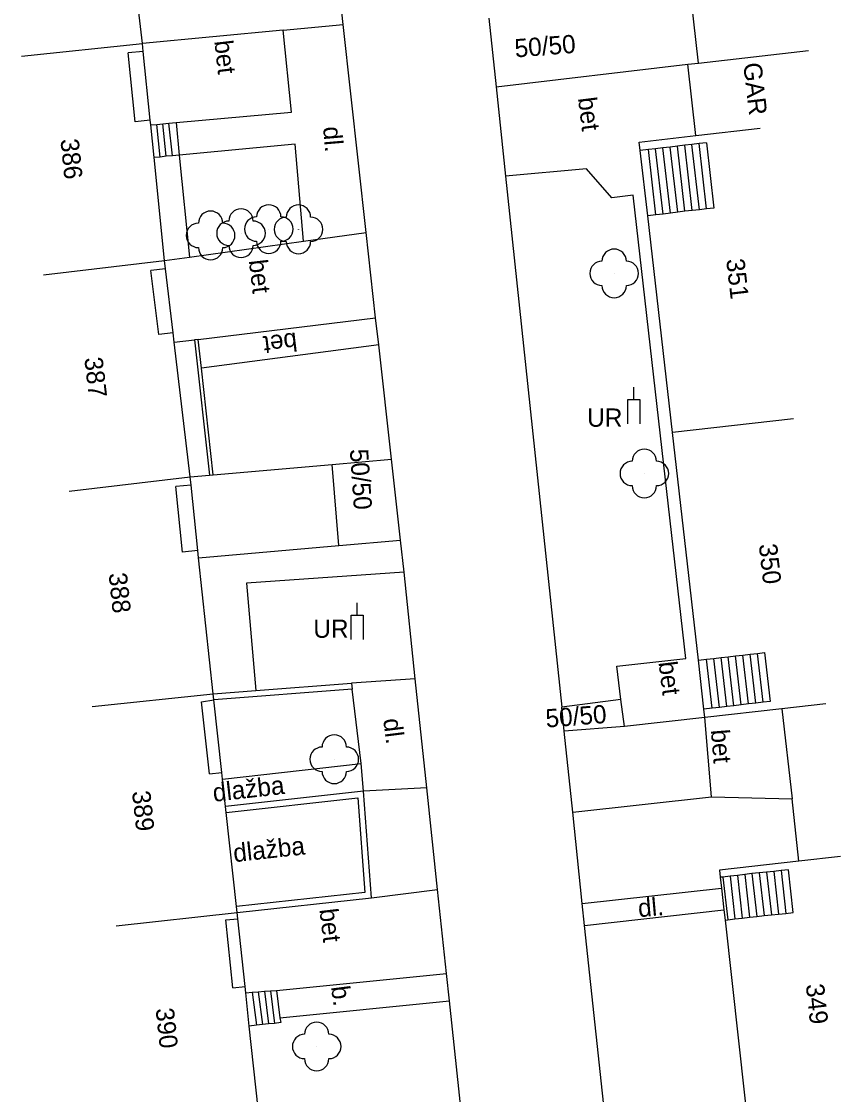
# Model space of a CAD drawing. Extents: x -544674 to -541478, y -1199076 to -1195527.
# Drawn here: x -542502.7 to -542469.05, y -1198467.22 to -1198423.14 of the extents above; entities that cross this region are included whole.
import ezdxf

# ---------------------------------------------------------------- set-up
doc = ezdxf.new("R2010")
doc.units = 0
for name, color, linetype in [('BUDOVY_MĚŘ', 7, 'Continuous'), ('POMOC_POPIS', 7, 'Continuous'), ('ROZHRANÍ_PLOCH', 7, 'Continuous'), ('ZELEŇ', 7, 'Continuous'), ('ZN_DOPLŇKOVÉ', 7, 'Continuous'), ('Č_POPIS_ORIENT', 7, 'Continuous')]:
    doc.layers.add(name, color=color, linetype=linetype)

msp = doc.modelspace()

# ---------------------------------------------------------------- linework, layer by layer
at = {"layer": 'BUDOVY_MĚŘ'}
for points in [[(-542497.73, -1198424.05), (-542498.24, -1198419.72)], [(-542502.7, -1198424.56), (-542497.73, -1198424.05)], [(-542497.7, -1198424.37), (-542497.73, -1198424.05)], [(-542497.41, -1198427.2), (-542497.7, -1198424.37)], [(-542474.89, -1198424.85), (-542470.36, -1198424.33)], [(-542475.33, -1198424.9), (-542474.89, -1198424.85)], [(-542474.99, -1198427.83), (-542475.33, -1198424.9)], [(-542497.39, -1198427.39), (-542497.41, -1198427.2)], [(-542497.25, -1198428.73), (-542497.39, -1198427.39)], [(-542474.99, -1198427.83), (-542472.35, -1198427.53)], [(-542477.28, -1198428.44), (-542477.32, -1198428.1), (-542474.99, -1198427.83)], [(-542476.97, -1198431.12), (-542477.28, -1198428.44)], [(-542496.82, -1198432.96), (-542497.25, -1198428.73)], [(-542475.95, -1198440.02), (-542476.97, -1198431.12)], [(-542501.79, -1198433.55), (-542496.82, -1198432.96)], [(-542496.78, -1198433.3), (-542496.82, -1198432.96)], [(-542496.47, -1198435.93), (-542496.78, -1198433.3)], [(-542496.42, -1198436.31), (-542496.47, -1198435.93)], [(-542495.77, -1198441.85), (-542496.42, -1198436.31)], [(-542470.98, -1198439.46), (-542475.95, -1198440.02)], [(-542474.89, -1198449.38), (-542475.95, -1198440.02)], [(-542500.74, -1198442.44), (-542495.77, -1198441.85)], [(-542495.73, -1198442.19), (-542495.77, -1198441.85)], [(-542495.45, -1198444.87), (-542495.73, -1198442.19)], [(-542495.42, -1198445.17), (-542495.45, -1198444.87)], [(-542494.83, -1198450.76), (-542495.42, -1198445.17)], [(-542474.66, -1198451.39), (-542474.89, -1198449.38)], [(-542499.8, -1198451.28), (-542494.83, -1198450.76)], [(-542494.8, -1198451.01), (-542494.83, -1198450.76)], [(-542494.47, -1198453.99), (-542494.8, -1198451.01)], [(-542474.62, -1198451.74), (-542474.66, -1198451.39)], [(-542471.46, -1198451.38), (-542474.62, -1198451.74)], [(-542469.65, -1198451.18), (-542471.46, -1198451.38)], [(-542494.44, -1198454.27), (-542494.47, -1198453.99)], [(-542494.32, -1198455.39), (-542494.44, -1198454.27)], [(-542494.29, -1198455.64), (-542494.32, -1198455.39)], [(-542493.87, -1198459.5), (-542494.29, -1198455.64)], [(-542470.76, -1198457.64), (-542474.02, -1198458), (-542473.99, -1198458.3)], [(-542469.05, -1198457.45), (-542470.76, -1198457.64)], [(-542472.09, -1198458.09), (-542472.39, -1198458.12)], [(-542471.79, -1198458.06), (-542472.09, -1198458.09)], [(-542471.49, -1198458.02), (-542471.79, -1198458.06)], [(-542471.3, -1198459.78), (-542471, -1198459.75), (-542471.19, -1198457.99), (-542471.49, -1198458.02)], [(-542473.88, -1198458.29), (-542473.99, -1198458.3)], [(-542473.99, -1198458.3), (-542473.94, -1198458.74)], [(-542473.58, -1198458.25), (-542473.88, -1198458.29)], [(-542473.28, -1198458.22), (-542473.58, -1198458.25)], [(-542472.98, -1198458.18), (-542473.28, -1198458.22)], [(-542472.69, -1198458.15), (-542472.98, -1198458.18)], [(-542472.39, -1198458.12), (-542472.69, -1198458.15)], [(-542473.94, -1198458.74), (-542473.84, -1198459.63)], [(-542498.81, -1198460.3), (-542493.84, -1198459.75)], [(-542493.84, -1198459.75), (-542493.87, -1198459.5)], [(-542493.81, -1198460), (-542493.84, -1198459.75)], [(-542473.84, -1198459.63), (-542473.79, -1198460.06)], [(-542472.49, -1198459.91), (-542472.19, -1198459.87)], [(-542472.19, -1198459.87), (-542471.89, -1198459.84)], [(-542471.89, -1198459.84), (-542471.6, -1198459.81)], [(-542471.6, -1198459.81), (-542471.3, -1198459.78)], [(-542493.51, -1198462.78), (-542493.81, -1198460)], [(-542473.79, -1198460.06), (-542473.68, -1198460.05)], [(-542473.79, -1198460.06), (-542472.71, -1198469.85)], [(-542473.68, -1198460.05), (-542473.39, -1198460.01)], [(-542473.39, -1198460.01), (-542473.09, -1198459.98)], [(-542473.09, -1198459.98), (-542472.79, -1198459.94)], [(-542472.79, -1198459.94), (-542472.49, -1198459.91)], [(-542493.48, -1198463.04), (-542493.51, -1198462.78)], [(-542493.34, -1198464.41), (-542493.48, -1198463.04)], [(-542494.76, -1198468.88), (-542492.88, -1198468.68), (-542493.34, -1198464.41)]]:
    msp.add_lwpolyline(points, dxfattribs=at)
at = {"layer": 'ROZHRANÍ_PLOCH'}
for points in [[(-542489.49, -1198423.27), (-542490.01, -1198418.46)], [(-542474.89, -1198424.85), (-542475.19, -1198422.17)], [(-542491.95, -1198423.5), (-542489.49, -1198423.27)], [(-542488.54, -1198431.81), (-542489.49, -1198423.27)], [(-542483.5, -1198423.01), (-542483.2, -1198425.83)], [(-542491.95, -1198423.5), (-542497.73, -1198424.05)], [(-542496.35, -1198427.29), (-542491.61, -1198426.86), (-542491.95, -1198423.5)], [(-542497.7, -1198424.37), (-542498.31, -1198424.43)], [(-542498.03, -1198427.27), (-542498.31, -1198424.43)], [(-542483.2, -1198425.83), (-542475.33, -1198424.9)], [(-542483.2, -1198425.83), (-542482.81, -1198429.49)], [(-542497.41, -1198427.2), (-542498.03, -1198427.27)], [(-542497.39, -1198427.39), (-542497.14, -1198427.37)], [(-542497.14, -1198427.37), (-542496.89, -1198427.34)], [(-542497, -1198428.71), (-542497.14, -1198427.37)], [(-542496.89, -1198427.34), (-542496.64, -1198427.32)], [(-542496.75, -1198428.68), (-542496.89, -1198427.34)], [(-542496.64, -1198427.32), (-542496.35, -1198427.29)], [(-542496.5, -1198428.66), (-542496.64, -1198427.32)], [(-542496.35, -1198427.29), (-542496.22, -1198428.63)], [(-542474.56, -1198428.13), (-542474.86, -1198428.16)], [(-542474.56, -1198428.13), (-542474.25, -1198430.81)], [(-542491.11, -1198432.17), (-542491.45, -1198428.18), (-542496.22, -1198428.63)], [(-542476.94, -1198428.4), (-542477.28, -1198428.44)], [(-542476.65, -1198428.37), (-542476.94, -1198428.4)], [(-542476.64, -1198431.08), (-542476.94, -1198428.4)], [(-542476.35, -1198428.33), (-542476.65, -1198428.37)], [(-542476.34, -1198431.05), (-542476.65, -1198428.37)], [(-542476.05, -1198428.3), (-542476.35, -1198428.33)], [(-542476.04, -1198431.01), (-542476.35, -1198428.33)], [(-542475.75, -1198428.26), (-542476.05, -1198428.3)], [(-542475.74, -1198430.98), (-542476.05, -1198428.3)], [(-542475.45, -1198428.22), (-542475.75, -1198428.26)], [(-542475.44, -1198430.94), (-542475.75, -1198428.26)], [(-542475.16, -1198428.19), (-542475.45, -1198428.22)], [(-542475.15, -1198430.91), (-542475.45, -1198428.22)], [(-542474.86, -1198428.16), (-542475.16, -1198428.19)], [(-542474.85, -1198430.88), (-542475.16, -1198428.19)], [(-542474.55, -1198430.84), (-542474.86, -1198428.16)], [(-542497, -1198428.71), (-542497.25, -1198428.73)], [(-542496.75, -1198428.68), (-542497, -1198428.71)], [(-542496.5, -1198428.66), (-542496.75, -1198428.68)], [(-542496.22, -1198428.63), (-542496.5, -1198428.66)], [(-542496.22, -1198428.63), (-542495.8, -1198432.82)], [(-542478.07, -1198451), (-542478.24, -1198449.63), (-542475.4, -1198449.31), (-542476.44, -1198440.16), (-542477.57, -1198430.28), (-542478.44, -1198430.38), (-542479.48, -1198429.2), (-542482.81, -1198429.49)], [(-542482.81, -1198429.49), (-542480.5, -1198451.31)], [(-542476.64, -1198431.08), (-542476.97, -1198431.12)], [(-542476.34, -1198431.05), (-542476.64, -1198431.08)], [(-542476.04, -1198431.01), (-542476.34, -1198431.05)], [(-542475.74, -1198430.98), (-542476.04, -1198431.01)], [(-542475.44, -1198430.94), (-542475.74, -1198430.98)], [(-542475.15, -1198430.91), (-542475.44, -1198430.94)], [(-542474.85, -1198430.88), (-542475.15, -1198430.91)], [(-542474.55, -1198430.84), (-542474.85, -1198430.88)], [(-542474.25, -1198430.81), (-542474.55, -1198430.84)], [(-542491.11, -1198432.17), (-542488.54, -1198431.81)], [(-542488.15, -1198435.31), (-542488.54, -1198431.81)], [(-542495.8, -1198432.82), (-542491.11, -1198432.17)], [(-542496.82, -1198432.96), (-542495.8, -1198432.82)], [(-542496.78, -1198433.3), (-542497.38, -1198433.37)], [(-542497.06, -1198436), (-542497.38, -1198433.37)], [(-542495.44, -1198436.2), (-542488.15, -1198435.31)], [(-542488.02, -1198436.43), (-542488.15, -1198435.31)], [(-542496.47, -1198435.93), (-542497.06, -1198436)], [(-542496.42, -1198436.31), (-542495.59, -1198436.22)], [(-542488.02, -1198436.43), (-542495.31, -1198437.39)], [(-542487.5, -1198441.12), (-542488.02, -1198436.43)], [(-542494.83, -1198441.77), (-542489.94, -1198441.34)], [(-542489.94, -1198441.34), (-542487.5, -1198441.12)], [(-542489.66, -1198444.67), (-542489.94, -1198441.34)], [(-542487.13, -1198444.45), (-542487.5, -1198441.12)], [(-542495.77, -1198441.85), (-542494.98, -1198441.78)], [(-542495.73, -1198442.19), (-542496.36, -1198442.25)], [(-542496.08, -1198444.94), (-542496.36, -1198442.25)], [(-542495.45, -1198444.87), (-542496.08, -1198444.94)], [(-542495.42, -1198445.17), (-542489.66, -1198444.67)], [(-542489.66, -1198444.67), (-542487.13, -1198444.45)], [(-542486.98, -1198445.76), (-542487.13, -1198444.45)], [(-542486.98, -1198445.76), (-542493.45, -1198446.22), (-542493.07, -1198450.62)], [(-542486.52, -1198450.15), (-542486.98, -1198445.76)], [(-542474.25, -1198449.31), (-542473.95, -1198449.27)], [(-542473.95, -1198449.27), (-542473.66, -1198449.24)], [(-542473.72, -1198451.28), (-542473.95, -1198449.27)], [(-542473.66, -1198449.24), (-542473.36, -1198449.2)], [(-542473.43, -1198451.25), (-542473.66, -1198449.24)], [(-542473.36, -1198449.2), (-542473.06, -1198449.17)], [(-542473.13, -1198451.22), (-542473.36, -1198449.2)], [(-542473.06, -1198449.17), (-542472.76, -1198449.13)], [(-542472.83, -1198451.18), (-542473.06, -1198449.17)], [(-542472.76, -1198449.13), (-542472.46, -1198449.1)], [(-542472.53, -1198451.15), (-542472.76, -1198449.13)], [(-542472.46, -1198449.1), (-542472.17, -1198449.07), (-542471.94, -1198451.08), (-542472.23, -1198451.11)], [(-542472.23, -1198451.11), (-542472.46, -1198449.1)], [(-542474.89, -1198449.38), (-542474.55, -1198449.34)], [(-542474.55, -1198449.34), (-542474.25, -1198449.31)], [(-542474.32, -1198451.35), (-542474.55, -1198449.34)], [(-542474.02, -1198451.32), (-542474.25, -1198449.31)], [(-542486.52, -1198450.15), (-542489.14, -1198450.32)], [(-542486.05, -1198454.63), (-542486.52, -1198450.15)], [(-542488.74, -1198453.63), (-542489.12, -1198450.57)], [(-542495.3, -1198451.09), (-542494.8, -1198451.01)], [(-542478.07, -1198451), (-542480.5, -1198451.31)], [(-542477.93, -1198452.1), (-542478.07, -1198451)], [(-542494.97, -1198454.05), (-542495.3, -1198451.09)], [(-542480.4, -1198452.29), (-542480.5, -1198451.31)], [(-542474.32, -1198451.35), (-542474.66, -1198451.39)], [(-542474.02, -1198451.32), (-542474.32, -1198451.35)], [(-542473.72, -1198451.28), (-542474.02, -1198451.32)], [(-542473.43, -1198451.25), (-542473.72, -1198451.28)], [(-542473.13, -1198451.22), (-542473.43, -1198451.25)], [(-542472.83, -1198451.18), (-542473.13, -1198451.22)], [(-542472.53, -1198451.15), (-542472.83, -1198451.18)], [(-542472.23, -1198451.11), (-542472.53, -1198451.15)], [(-542471.46, -1198451.38), (-542471.04, -1198455.08)], [(-542474.62, -1198451.74), (-542477.93, -1198452.1)], [(-542474.35, -1198454.99), (-542474.62, -1198451.74)], [(-542477.93, -1198452.1), (-542480.4, -1198452.29)], [(-542480.05, -1198455.63), (-542480.4, -1198452.29)], [(-542494.44, -1198454.27), (-542488.74, -1198453.63)], [(-542488.65, -1198454.76), (-542488.74, -1198453.63)], [(-542494.97, -1198454.05), (-542494.47, -1198453.99)], [(-542486.05, -1198454.63), (-542488.65, -1198454.76)], [(-542485.61, -1198458.8), (-542486.05, -1198454.63)], [(-542480.05, -1198455.63), (-542474.35, -1198454.99)], [(-542474.35, -1198454.99), (-542471.04, -1198455.08)], [(-542470.76, -1198457.64), (-542471.04, -1198455.08)], [(-542479.66, -1198459.38), (-542480.05, -1198455.63)], [(-542472.09, -1198458.09), (-542471.89, -1198459.84)], [(-542471.79, -1198458.06), (-542471.6, -1198459.81)], [(-542471.49, -1198458.02), (-542471.3, -1198459.78)], [(-542473.88, -1198458.29), (-542473.68, -1198460.05)], [(-542473.58, -1198458.25), (-542473.39, -1198460.01)], [(-542473.28, -1198458.22), (-542473.09, -1198459.98)], [(-542472.98, -1198458.18), (-542472.79, -1198459.94)], [(-542472.69, -1198458.15), (-542472.49, -1198459.91)], [(-542472.39, -1198458.12), (-542472.19, -1198459.87)], [(-542488.32, -1198459.14), (-542485.61, -1198458.8)], [(-542485.24, -1198462.25), (-542485.61, -1198458.8)], [(-542479.66, -1198459.38), (-542473.94, -1198458.74)], [(-542479.57, -1198460.28), (-542479.66, -1198459.38)], [(-542479.57, -1198460.28), (-542473.84, -1198459.63)], [(-542494.31, -1198460.05), (-542493.81, -1198460)], [(-542494.01, -1198462.84), (-542494.31, -1198460.05)], [(-542477.21, -1198482.02), (-542477.35, -1198480.95), (-542479.57, -1198460.28)], [(-542492.22, -1198462.95), (-542485.24, -1198462.25)], [(-542485.12, -1198463.37), (-542485.24, -1198462.25)], [(-542494.01, -1198462.84), (-542493.51, -1198462.78)], [(-542492.47, -1198462.97), (-542492.22, -1198462.95)], [(-542492.22, -1198462.95), (-542492.08, -1198464.07)], [(-542493.48, -1198463.04), (-542493.22, -1198463.02)], [(-542493.22, -1198463.02), (-542492.97, -1198463)], [(-542493.22, -1198463.02), (-542493.04, -1198464.38)], [(-542492.97, -1198463), (-542492.72, -1198462.98)], [(-542492.97, -1198463), (-542492.8, -1198464.35)], [(-542492.72, -1198462.98), (-542492.47, -1198462.97)], [(-542492.72, -1198462.98), (-542492.55, -1198464.32)], [(-542492.47, -1198462.97), (-542492.3, -1198464.3)], [(-542492.08, -1198464.07), (-542485.12, -1198463.37)], [(-542484.3, -1198471.13), (-542485.12, -1198463.37)], [(-542492.08, -1198464.07), (-542492.05, -1198464.27), (-542492.3, -1198464.3)], [(-542493.04, -1198464.38), (-542493.34, -1198464.41)], [(-542492.8, -1198464.35), (-542493.04, -1198464.38)], [(-542492.55, -1198464.32), (-542492.8, -1198464.35)], [(-542492.3, -1198464.3), (-542492.55, -1198464.32)]]:
    msp.add_lwpolyline(points, dxfattribs=at)
at = {"layer": 'ZELEŇ'}
for centre in [(-542494.93, -1198431.93), (-542493.68, -1198431.84), (-542492.54, -1198431.67), (-542491.32, -1198431.68), (-542478.35, -1198433.49), (-542477.11, -1198441.71), (-542489.85, -1198453.45), (-542490.57, -1198465.25)]:
    msp.add_circle(centre, 0.0005, dxfattribs=at)
for centre, start, end in [((-542492.54, -1198431.17), 0, 180), ((-542491.32, -1198431.18), 0, 180), ((-542494.93, -1198431.43), 0, 180), ((-542493.68, -1198431.34), 0, 180), ((-542493.04, -1198431.67), 90, 270), ((-542491.82, -1198431.68), 90, 270), ((-542492.04, -1198431.67), 270, 90), ((-542490.82, -1198431.68), 270, 90), ((-542495.43, -1198431.93), 90, 270), ((-542494.18, -1198431.84), 90, 270), ((-542494.43, -1198431.93), 270, 90), ((-542493.18, -1198431.84), 270, 90), ((-542494.93, -1198432.43), 180, 360), ((-542493.68, -1198432.34), 180, 360), ((-542492.54, -1198432.17), 180, 360), ((-542491.32, -1198432.18), 180, 360), ((-542478.35, -1198432.99), 0, 180), ((-542478.85, -1198433.49), 90, 270), ((-542477.85, -1198433.49), 270, 90), ((-542478.35, -1198433.99), 180, 360), ((-542477.11, -1198441.21), 0, 180), ((-542477.61, -1198441.71), 90, 270), ((-542476.61, -1198441.71), 270, 90), ((-542477.11, -1198442.21), 180, 360), ((-542489.85, -1198452.95), 0, 180), ((-542490.35, -1198453.45), 90, 270), ((-542489.35, -1198453.45), 270, 90), ((-542489.85, -1198453.95), 180, 360), ((-542490.57, -1198464.75), 0, 180), ((-542491.07, -1198465.25), 90, 270), ((-542490.07, -1198465.25), 270, 90), ((-542490.57, -1198465.75), 180, 360)]:
    msp.add_arc(centre, 0.5, start, end, dxfattribs=at)
at = {"layer": 'ZN_DOPLŇKOVÉ'}
for p, q in [((-542477.54, -1198438.67), (-542477.54, -1198438.17)), ((-542488.91, -1198447.53), (-542488.91, -1198447.03))]:
    msp.add_line(p, q, dxfattribs=at)
for points in [[(-542495.44, -1198436.2), (-542495.59, -1198436.22)], [(-542495.59, -1198436.22), (-542494.98, -1198441.78)], [(-542495.31, -1198437.39), (-542495.44, -1198436.2)], [(-542494.83, -1198441.77), (-542495.31, -1198437.39)], [(-542477.79, -1198439.67), (-542477.79, -1198438.67), (-542477.29, -1198438.67), (-542477.29, -1198439.67)], [(-542494.98, -1198441.78), (-542494.83, -1198441.77)], [(-542489.16, -1198448.53), (-542489.16, -1198447.53), (-542488.66, -1198447.53), (-542488.66, -1198448.53)], [(-542489.12, -1198450.57), (-542494.8, -1198451.01)], [(-542493.07, -1198450.62), (-542489.14, -1198450.32)], [(-542489.14, -1198450.32), (-542489.12, -1198450.57)], [(-542494.83, -1198450.76), (-542493.07, -1198450.62)], [(-542488.65, -1198454.76), (-542494.32, -1198455.39)], [(-542488.32, -1198459.14), (-542488.65, -1198454.76)], [(-542494.29, -1198455.64), (-542488.88, -1198455.04), (-542488.59, -1198458.92), (-542493.87, -1198459.5)], [(-542493.84, -1198459.75), (-542488.32, -1198459.14)]]:
    msp.add_lwpolyline(points, dxfattribs=at)

# ---------------------------------------------------------------- texts
at = {"layer": 'POMOC_POPIS'}
for s, rotation, p in [('50/50', 4.45, (-542482.41, -1198424.62)), ('bet', 276.57, (-542494.78, -1198423.95)), ('GAR', 276.56, (-542473.05, -1198424.87)), ('bet', 277.15, (-542479.84, -1198426.29)), ('dl.', 274.82, (-542490.31, -1198427.48)), ('bet', 276.74, (-542493.36, -1198432.96)), ('bet', 186.92, (-542491.42, -1198435.91)), ('50/50', 273.9, (-542489.21, -1198440.72)), ('bet', 277.15, (-542476.53, -1198449.47)), ('50/50', 4.45, (-542481.14, -1198452.15)), ('dl.', 277.08, (-542487.84, -1198451.81)), ('bet', 274.75, (-542474.38, -1198452.25)), ('dlažba', 6.41, (-542494.8, -1198455.2)), ('dlažba', 6.28, (-542493.96, -1198457.68)), ('dl.', 5.04, (-542477.34, -1198459.94)), ('bet', 276.74, (-542490.46, -1198459.62)), ('b.', 277.34, (-542489.98, -1198462.8))]:
    msp.add_text(s, height=0.75, rotation=rotation, dxfattribs=at).set_placement(p)
for p in [(-542479.46, -1198439.79), (-542490.71, -1198448.46)]:
    msp.add_text('UR', height=0.75, dxfattribs=at).set_placement(p)
at = {"layer": 'Č_POPIS_ORIENT'}
for s, rotation, p in [('386', 275.83, (-542501.1, -1198427.99)), ('351', 276.56, (-542473.75, -1198432.92)), ('387', 276.74, (-542500.12, -1198436.97)), ('350', 276.47, (-542472.41, -1198444.63)), ('388', 276.02, (-542499.12, -1198445.82)), ('389', 276.28, (-542498.16, -1198454.78)), ('349', 276.31, (-542470.48, -1198462.71)), ('390', 276.14, (-542497.19, -1198463.7))]:
    msp.add_text(s, height=0.75, rotation=rotation, dxfattribs=at).set_placement(p)

doc.saveas('drawing.dxf')
